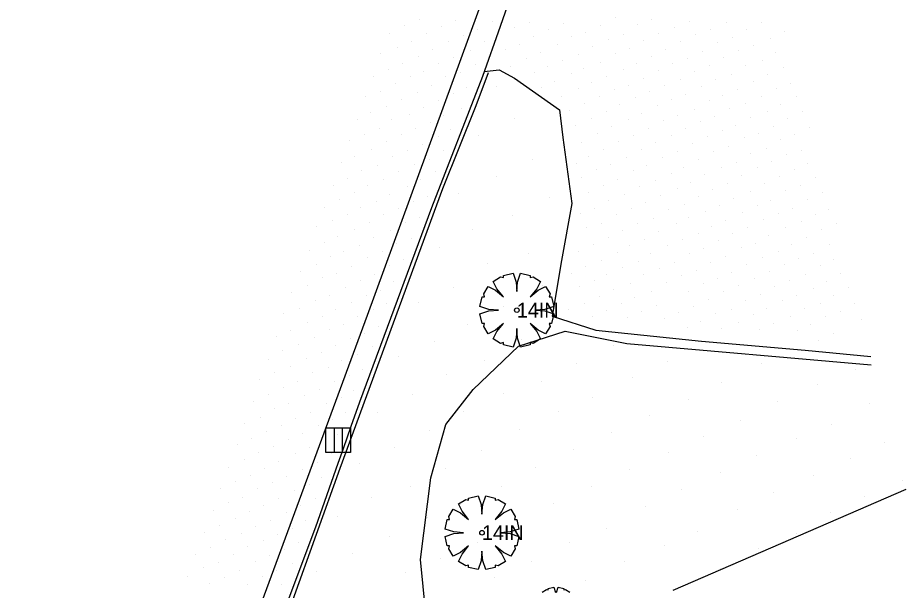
# Model space of a CAD drawing. Extents: x 1729983 to 1730242, y 468641 to 469019.
# Drawn here: x 1730133.1 to 1730241.6, y 468879.2 to 468949.2 of the extents above; entities that cross this region are included whole.
import ezdxf

# ---------------------------------------------------------------- set-up
doc = ezdxf.new("R2010")
doc.units = 0
for name, color, linetype in [('Default', 7, 'Continuous'), ('S_Curb_Type_1', 7, 'Continuous'), ('S_Drainage_CB', 7, 'Continuous'), ('S_Fencing_ChainLink', 7, 'Continuous'), ('S_Ground_SpotElevation', 7, 'Continuous'), ('S_Roadway_Drive_Paved', 7, 'Continuous'), ('S_Roadway_Edge_Pavement', 7, 'Continuous'), ('S_Roadway_Painted_Lines', 7, 'Continuous'), ('S_Text', 7, 'Continuous'), ('S_Trees_Bush_Line', 7, 'Continuous'), ('S_Trees_Decid_NonPay', 7, 'Continuous'), ('S_Trees_Decid_Pay', 7, 'Continuous')]:
    doc.layers.add(name, color=color, linetype=linetype)

# ---------------------------------------------------------------- blocks, each defined once
blk = doc.blocks.new('POINT_DISPLAY')
at = {"layer": 'Default'}
blk.add_line((0, 0), (0, 0), dxfattribs=at)

msp = doc.modelspace()

# ---------------------------------------------------------------- linework, layer by layer
at = {"layer": 'S_Curb_Type_1'}
msp.add_lwpolyline([(1730166.7, 468878.04), (1730172.48, 468894.17), (1730178.99, 468911.93), (1730185.01, 468928.36), (1730189.07, 468938.51), (1730190.59, 468942.51)], dxfattribs=at)
at = {"layer": 'S_Drainage_CB'}
for p, q in [((1730171.73, 468899.1), (1730171.73, 468896.1)), ((1730172.73, 468899.1), (1730172.73, 468896.1))]:
    msp.add_line(p, q, dxfattribs=at)
msp.add_lwpolyline([(1730170.73, 468899.1), (1730173.73, 468899.1), (1730173.73, 468896.1), (1730170.73, 468896.1)], close=True, dxfattribs=at)
at = {"layer": 'S_Fencing_ChainLink'}
msp.add_line((1730213.16, 468879.27), (1730241.65, 468891.6), dxfattribs=at)
at = {"layer": 'S_Roadway_Drive_Paved'}
msp.add_lwpolyline([(1730190.08, 468942.66), (1730191.89, 468942.87), (1730193.76, 468941.82), (1730199.29, 468937.96), (1730199.68, 468934.57), (1730200.79, 468926.52), (1730199.5, 468919.56), (1730198.39, 468912.74), (1730203.72, 468911.04), (1730216.64, 468909.68), (1730229.29, 468908.57), (1730237.33, 468907.81)], dxfattribs=at)
at = {"layer": 'S_Roadway_Edge_Pavement'}
msp.add_lwpolyline([(1730202.63, 468977.5), (1730198.74, 468966.66), (1730194.38, 468954.96), (1730192.03, 468948.15), (1730189.86, 468942.05), (1730183.64, 468926), (1730174.83, 468902.22), (1730173.78, 468899.25), (1730172.82, 468896.55), (1730172.2, 468894.75), (1730169.44, 468886.97), (1730164.5, 468873.71)], dxfattribs=at)
at = {"layer": 'S_Roadway_Painted_Lines'}
msp.add_lwpolyline([(1730094.8, 468656.26), (1730095.17, 468660.96), (1730096.08, 468669.98), (1730097.64, 468680.77), (1730099.58, 468691.95), (1730101.13, 468699.69), (1730104.77, 468714.07), (1730108.65, 468727.01), (1730112.54, 468738.83), (1730119.79, 468759.43), (1730137.2, 468807.81), (1730148.9, 468839.72), (1730160.49, 468871.27), (1730175.8, 468912.85), (1730190.41, 468952.88), (1730200.04, 468978.35)], dxfattribs=at)
at = {"layer": 'S_Trees_Bush_Line'}
msp.add_lwpolyline([(1730184.47, 468866.09), (1730183.27, 468873.09), (1730182.28, 468883.02), (1730183.53, 468892.98), (1730185.39, 468899.51), (1730188.73, 468903.8), (1730194.28, 468909.06), (1730199.95, 468910.92), (1730207.49, 468909.42), (1730237.35, 468906.81)], dxfattribs=at)
at = {"layer": 'S_Trees_Decid_NonPay'}
for points in [[(1730197.16, 468879.02), (1730197.69, 468879.34), (1730197.9, 468879.29), (1730197.9, 468879.45), (1730198.59, 468879.61), (1730198.8, 468878.97)], [(1730198.91, 468878.97), (1730199.12, 468879.61), (1730199.81, 468879.45), (1730199.81, 468879.29), (1730200.02, 468879.34), (1730200.55, 468879.02)]]:
    msp.add_lwpolyline(points, dxfattribs=at)
at = {"layer": 'S_Trees_Decid_Pay'}
for points in [[(1730191.81, 468913.48), (1730190.64, 468913.57), (1730189.55, 468913.93), (1730189.82, 468915.11), (1730190.1, 468915.11), (1730190.01, 468915.47), (1730190.55, 468916.37), (1730191.45, 468915.92), (1730192.44, 468915.11), (1730191.63, 468916.1), (1730191.18, 468917), (1730192.08, 468917.54), (1730192.44, 468917.45), (1730192.44, 468917.72), (1730193.61, 468918), (1730193.97, 468916.91), (1730194.06, 468915.74), (1730194.16, 468916.91), (1730194.52, 468918), (1730195.69, 468917.72), (1730195.69, 468917.45), (1730196.05, 468917.54), (1730196.95, 468917), (1730196.5, 468916.1), (1730195.69, 468915.11), (1730196.68, 468915.92), (1730197.58, 468916.37), (1730198.12, 468915.47), (1730198.03, 468915.11), (1730198.31, 468915.11), (1730198.58, 468913.93), (1730197.49, 468913.57), (1730196.32, 468913.48), (1730197.49, 468913.39), (1730198.58, 468913.03), (1730198.31, 468911.86), (1730198.03, 468911.86), (1730198.12, 468911.5), (1730197.58, 468910.6), (1730196.68, 468911.05), (1730195.69, 468911.86), (1730196.5, 468910.87), (1730196.95, 468909.97), (1730196.05, 468909.42), (1730195.69, 468909.51), (1730195.69, 468909.24), (1730194.52, 468908.97), (1730194.16, 468910.06), (1730194.06, 468911.23), (1730193.97, 468910.06), (1730193.61, 468908.97), (1730192.44, 468909.24), (1730192.44, 468909.51), (1730192.08, 468909.42), (1730191.18, 468909.97), (1730191.63, 468910.87), (1730192.44, 468911.86), (1730191.45, 468911.05), (1730190.55, 468910.6), (1730190.01, 468911.5), (1730190.1, 468911.86), (1730189.82, 468911.86), (1730189.55, 468913.03), (1730190.64, 468913.39), (1730191.81, 468913.48)], [(1730187.54, 468886.28), (1730186.37, 468886.37), (1730185.28, 468886.73), (1730185.56, 468887.91), (1730185.83, 468887.91), (1730185.74, 468888.27), (1730186.28, 468889.17), (1730187.18, 468888.72), (1730188.17, 468887.91), (1730187.36, 468888.9), (1730186.91, 468889.8), (1730187.81, 468890.34), (1730188.17, 468890.25), (1730188.17, 468890.52), (1730189.34, 468890.8), (1730189.71, 468889.71), (1730189.8, 468888.54), (1730189.89, 468889.71), (1730190.25, 468890.8), (1730191.42, 468890.52), (1730191.42, 468890.25), (1730191.78, 468890.34), (1730192.68, 468889.8), (1730192.23, 468888.9), (1730191.42, 468887.91), (1730192.41, 468888.72), (1730193.32, 468889.17), (1730193.86, 468888.27), (1730193.77, 468887.91), (1730194.04, 468887.91), (1730194.31, 468886.73), (1730193.23, 468886.37), (1730192.05, 468886.28), (1730193.23, 468886.19), (1730194.31, 468885.83), (1730194.04, 468884.66), (1730193.77, 468884.66), (1730193.86, 468884.3), (1730193.32, 468883.4), (1730192.41, 468883.85), (1730191.42, 468884.66), (1730192.23, 468883.67), (1730192.68, 468882.77), (1730191.78, 468882.22), (1730191.42, 468882.31), (1730191.42, 468882.04), (1730190.25, 468881.77), (1730189.89, 468882.86), (1730189.8, 468884.03), (1730189.71, 468882.86), (1730189.34, 468881.77), (1730188.17, 468882.04), (1730188.17, 468882.31), (1730187.81, 468882.22), (1730186.91, 468882.77), (1730187.36, 468883.67), (1730188.17, 468884.66), (1730187.18, 468883.85), (1730186.28, 468883.4), (1730185.74, 468884.3), (1730185.83, 468884.66), (1730185.56, 468884.66), (1730185.28, 468885.83), (1730186.37, 468886.19), (1730187.54, 468886.28)]]:
    msp.add_lwpolyline(points, dxfattribs=at)
for centre in [(1730194.06, 468913.48), (1730189.8, 468886.28)]:
    msp.add_circle(centre, 0.283, dxfattribs=at)

# ---------------------------------------------------------------- block references
at = {"layer": 'S_Ground_SpotElevation'}
for p in [(1730180.32, 468948.21), (1730182.17, 468948.97), (1730186.61, 468948.84), (1730191.05, 468948.8), (1730195.6, 468948.64), (1730199.78, 468948.56), (1730204.25, 468948.33), (1730206.06, 468949.19), (1730208.76, 468948.37), (1730210.5, 468949.03), (1730215.13, 468948.78), (1730219.62, 468948.6), (1730223.95, 468948.63), (1730178.44, 468947.25), (1730183.07, 468947.27), (1730184.9, 468948.11), (1730189.22, 468947.78), (1730193.74, 468947.98), (1730197.98, 468947.81), (1730202.51, 468947.45), (1730207.06, 468947.18), (1730211.36, 468947.34), (1730213.3, 468948.04), (1730215.88, 468947.22), (1730217.72, 468947.8), (1730222.18, 468947.8), (1730226.76, 468947.52), (1730181.13, 468946.34), (1730185.72, 468946.31), (1730187.51, 468947.01), (1730190.07, 468946.29), (1730191.71, 468947), (1730194.36, 468945.98), (1730196.13, 468946.9), (1730199.04, 468945.98), (1730200.75, 468946.87), (1730205.2, 468946.56), (1730209.51, 468946.38), (1730214.03, 468946.34), (1730218.61, 468946.21), (1730220.38, 468946.83), (1730225, 468946.64), (1730177.38, 468944.89), (1730179.42, 468945.63), (1730183.74, 468945.28), (1730188.34, 468945.21), (1730192.69, 468945.29), (1730197.01, 468944.93), (1730203.34, 468945.76), (1730206.16, 468944.88), (1730207.79, 468945.49), (1730212.18, 468945.38), (1730216.79, 468945.08), (1730221.2, 468945.25), (1730222.93, 468945.87), (1730225.7, 468944.97), (1730182, 468944.47), (1730186.34, 468944.41), (1730190.71, 468944.28), (1730195.28, 468944.22), (1730199.59, 468944.04), (1730201.56, 468944.7), (1730210.51, 468944.47), (1730214.94, 468944.28), (1730219.32, 468944.35), (1730224.05, 468944.05), (1730178.39, 468942.88), (1730180.09, 468943.67), (1730184.54, 468943.67), (1730189.02, 468943.47), (1730193.31, 468943.29), (1730197.79, 468943.24), (1730202.25, 468943.06), (1730204.26, 468943.69), (1730207.04, 468942.88), (1730208.63, 468943.65), (1730211.32, 468942.79), (1730213.09, 468943.6), (1730217.55, 468943.33), (1730222.02, 468943.43), (1730226.6, 468943.1), (1730176.57, 468942.06), (1730181.11, 468942), (1730182.69, 468942.66), (1730185.38, 468941.98), (1730187.19, 468942.53), (1730196.21, 468942.48), (1730200.69, 468942.38), (1730204.96, 468942), (1730209.48, 468941.77), (1730214.1, 468941.69), (1730215.73, 468942.67), (1730218.33, 468941.71), (1730220.27, 468942.34), (1730224.67, 468942.29), (1730179.28, 468941.2), (1730183.59, 468940.91), (1730187.94, 468940.73), (1730191.59, 468940.86), (1730197.05, 468940.73), (1730198.69, 468941.41), (1730201.58, 468940.53), (1730203.23, 468941.32), (1730207.7, 468940.91), (1730212.09, 468940.9), (1730216.59, 468940.83), (1730222.96, 468941.41), (1730225.77, 468940.62), (1730227.45, 468941.21), (1730175.54, 468939.55), (1730177.43, 468940.2), (1730181.93, 468940.05), (1730186.32, 468939.94), (1730199.48, 468939.61), (1730204.12, 468939.61), (1730206, 468940.41), (1730210.23, 468940.2), (1730214.7, 468939.89), (1730219.18, 468939.69), (1730221.03, 468940.5), (1730223.92, 468939.56), (1730228.18, 468939.6), (1730178.16, 468938.4), (1730180.01, 468939.21), (1730184.47, 468939.12), (1730202.28, 468938.71), (1730206.66, 468938.57), (1730208.57, 468939.43), (1730211.28, 468938.45), (1730212.92, 468939.19), (1730217.6, 468939.05), (1730221.95, 468938.74), (1730226.27, 468938.62), (1730176.22, 468937.59), (1730180.91, 468937.37), (1730182.63, 468938.23), (1730185.12, 468937.31), (1730187.24, 468938.12), (1730200.5, 468937.92), (1730204.98, 468937.73), (1730209.31, 468937.52), (1730213.74, 468937.32), (1730215.71, 468937.97), (1730220.09, 468938.13), (1730224.68, 468937.75), (1730229.02, 468937.77), (1730174.58, 468936.82), (1730178.79, 468936.74), (1730183.45, 468936.45), (1730193.83, 468936.88), (1730203.18, 468936.93), (1730207.66, 468936.73), (1730211.99, 468936.64), (1730216.53, 468936.52), (1730218.22, 468937.16), (1730222.64, 468937.05), (1730227.19, 468936.91), (1730177.23, 468935.72), (1730181.63, 468935.65), (1730185.97, 468935.6), (1730201.25, 468936.05), (1730205.64, 468935.88), (1730210.2, 468935.71), (1730214.73, 468935.64), (1730219.17, 468935.46), (1730220.84, 468936.07), (1730225.47, 468935.95), (1730229.84, 468935.81), (1730173.58, 468934.21), (1730175.49, 468934.94), (1730178.13, 468934.1), (1730179.96, 468934.93), (1730184.45, 468934.7), (1730189.34, 468934.82), (1730202, 468934.03), (1730203.86, 468935.05), (1730206.49, 468934.08), (1730208.29, 468934.79), (1730212.96, 468934.83), (1730217.33, 468934.68), (1730221.87, 468934.53), (1730223.56, 468935.03), (1730226.25, 468934.37), (1730228, 468934.92), (1730176.3, 468933.07), (1730180.73, 468933.04), (1730182.58, 468933.78), (1730185.14, 468933.03), (1730204.67, 468933.17), (1730209.29, 468933.12), (1730211.05, 468933.98), (1730215.56, 468933.81), (1730219.9, 468933.5), (1730224.55, 468933.24), (1730228.89, 468933.04), (1730174.25, 468932.27), (1730178.89, 468932.22), (1730183.37, 468931.92), (1730196.03, 468931.93), (1730202.85, 468932.28), (1730207.43, 468932.16), (1730211.9, 468932.15), (1730213.65, 468932.86), (1730216.31, 468931.86), (1730218.09, 468932.84), (1730222.64, 468932.59), (1730227.02, 468932.47), (1730172.58, 468931.51), (1730176.98, 468931.2), (1730181.6, 468931.3), (1730201.35, 468931.4), (1730205.55, 468931.28), (1730209.9, 468931.2), (1730214.43, 468930.96), (1730219.09, 468930.86), (1730220.87, 468931.51), (1730223.47, 468930.86), (1730225.23, 468931.62), (1730229.62, 468931.45), (1730175.02, 468930.51), (1730179.54, 468930.45), (1730184.08, 468930.37), (1730191.59, 468929.81), (1730201.91, 468929.71), (1730203.76, 468930.64), (1730208.27, 468930.52), (1730212.94, 468930.21), (1730217.04, 468930.11), (1730221.57, 468929.93), (1730226.12, 468929.83), (1730228, 468930.65), (1730230.55, 468929.68), (1730171.62, 468928.72), (1730173.36, 468929.62), (1730175.85, 468928.7), (1730177.74, 468929.45), (1730180.67, 468928.6), (1730182.32, 468929.41), (1730204.65, 468928.71), (1730206.34, 468929.43), (1730209.06, 468928.62), (1730210.97, 468929.3), (1730215.31, 468929.07), (1730219.75, 468929.01), (1730224.29, 468929), (1730228.67, 468928.72), (1730174.2, 468927.81), (1730178.51, 468927.6), (1730186.88, 468927.73), (1730202.82, 468927.82), (1730207.16, 468927.56), (1730213.72, 468928.33), (1730218, 468928.27), (1730222.65, 468928.04), (1730226.88, 468928.07), (1730231.4, 468927.81), (1730172.34, 468926.99), (1730176.96, 468926.74), (1730181.49, 468926.73), (1730183.19, 468927.42), (1730198.03, 468927.27), (1730205.32, 468926.89), (1730209.84, 468926.68), (1730211.62, 468927.45), (1730216.25, 468927.39), (1730220.56, 468927.12), (1730225.1, 468926.91), (1730229.56, 468926.98), (1730170.56, 468926.06), (1730174.92, 468925.99), (1730179.58, 468925.87), (1730201.87, 468925.34), (1730203.55, 468925.94), (1730208.02, 468925.96), (1730212.65, 468925.84), (1730214.49, 468926.37), (1730217.07, 468925.51), (1730218.86, 468926.25), (1730221.67, 468925.41), (1730223.43, 468926.27), (1730227.78, 468925.92), (1730232.17, 468925.82), (1730171.51, 468924.47), (1730173.31, 468925.2), (1730177.76, 468925.16), (1730182.19, 468924.75), (1730193.48, 468925.07), (1730206.23, 468925.12), (1730210.71, 468924.71), (1730215.09, 468924.79), (1730219.59, 468924.49), (1730224.18, 468924.51), (1730226.03, 468925.26), (1730228.81, 468924.29), (1730230.57, 468925.22), (1730169.55, 468923.75), (1730174.18, 468923.35), (1730176.04, 468924.18), (1730178.58, 468923.18), (1730180.46, 468924.19), (1730188.67, 468923.36), (1730202.63, 468923.52), (1730204.42, 468924.05), (1730206.98, 468923.18), (1730208.79, 468924.1), (1730213.56, 468924.05), (1730217.83, 468923.66), (1730222.22, 468923.62), (1730226.88, 468923.59), (1730231.24, 468923.31), (1730233.12, 468924.05), (1730172.13, 468922.52), (1730176.57, 468922.33), (1730181.2, 468922.19), (1730205.28, 468922.3), (1730209.69, 468922.17), (1730211.43, 468923.07), (1730214.29, 468922.17), (1730216.2, 468922.85), (1730220.42, 468922.79), (1730224.85, 468922.56), (1730229.46, 468922.4), (1730170.52, 468921.72), (1730174.85, 468921.43), (1730179.34, 468921.6), (1730184.57, 468921.12), (1730203.4, 468921.56), (1730207.85, 468921.43), (1730212.47, 468921.33), (1730216.91, 468921.06), (1730218.71, 468921.99), (1730221.53, 468921.08), (1730223.28, 468921.64), (1730227.66, 468921.49), (1730232.32, 468921.48), (1730168.72, 468920.83), (1730171.24, 468920.06), (1730172.89, 468920.68), (1730175.75, 468919.89), (1730177.63, 468920.65), (1730195.5, 468920.38), (1730201.57, 468920.61), (1730206.33, 468920.48), (1730210.44, 468920.4), (1730215.17, 468920.4), (1730219.56, 468920.01), (1730224.02, 468919.9), (1730225.99, 468920.65), (1730230.33, 468920.45), (1730169.59, 468919.03), (1730173.88, 468918.85), (1730178.48, 468918.89), (1730180.24, 468919.65), (1730190.51, 468919.17), (1730202.46, 468918.82), (1730204.4, 468919.53), (1730208.91, 468919.45), (1730213.29, 468919.26), (1730217.75, 468919.32), (1730222.12, 468919.12), (1730226.75, 468919), (1730228.52, 468919.77), (1730231.19, 468918.89), (1730232.81, 468919.69), (1730167.57, 468918.18), (1730172.08, 468917.92), (1730176.66, 468917.79), (1730200.74, 468918.02), (1730205.04, 468917.81), (1730207.02, 468918.74), (1730209.54, 468917.8), (1730211.53, 468918.6), (1730214.23, 468917.74), (1730216, 468918.34), (1730220.32, 468918.14), (1730224.89, 468918.15), (1730229.29, 468917.8), (1730233.65, 468917.91), (1730170.36, 468917.41), (1730174.91, 468917.16), (1730179.03, 468916.93), (1730203.54, 468917.12), (1730207.92, 468916.77), (1730212.3, 468916.84), (1730216.88, 468916.68), (1730218.53, 468917.36), (1730223.11, 468917.39), (1730227.44, 468917.1), (1730231.92, 468917.01), (1730166.47, 468915.6), (1730168.5, 468916.44), (1730173.09, 468916.27), (1730177.44, 468915.94), (1730186.28, 468916.3), (1730197.15, 468916.51), (1730201.69, 468916.35), (1730205.87, 468916.06), (1730210.47, 468915.79), (1730215.03, 468915.8), (1730219.36, 468915.72), (1730221.2, 468916.49), (1730225.56, 468916.35), (1730230.34, 468916.16), (1730234.61, 468916.21), (1730169.44, 468914.67), (1730171.22, 468915.33), (1730173.81, 468914.47), (1730175.68, 468915.25), (1730204.16, 468915.09), (1730208.48, 468915.03), (1730217.49, 468914.79), (1730222, 468914.63), (1730223.79, 468915.44), (1730226.52, 468914.66), (1730228.25, 468915.28), (1730232.8, 468915.25), (1730167.5, 468913.74), (1730171.87, 468913.57), (1730176.56, 468913.58), (1730178.12, 468914.32), (1730182.01, 468914.4), (1730192.48, 468913.96), (1730200.43, 468913.61), (1730202.37, 468914.31), (1730204.96, 468913.4), (1730206.87, 468914.33), (1730211.14, 468914.06), (1730215.65, 468913.95), (1730220.27, 468913.62), (1730224.63, 468913.64), (1730229.16, 468913.67), (1730231.12, 468914.28), (1730235.37, 468914.32), (1730165.5, 468913.01), (1730170.28, 468912.69), (1730174.64, 468912.72), (1730203.3, 468912.69), (1730207.58, 468912.57), (1730209.35, 468913.31), (1730212.06, 468912.45), (1730213.85, 468913.15), (1730218.37, 468913.11), (1730222.95, 468912.94), (1730227.46, 468912.65), (1730231.83, 468912.65), (1730233.58, 468913.36), (1730236.19, 468912.3), (1730168.46, 468911.98), (1730172.91, 468911.69), (1730177.19, 468911.53), (1730188.01, 468911.77), (1730214.88, 468911.34), (1730216.47, 468912.06), (1730219.12, 468911.25), (1730221.18, 468911.94), (1730225.47, 468911.84), (1730229.91, 468911.74), (1730164.7, 468910.21), (1730166.37, 468910.97), (1730169.29, 468910.19), (1730171.12, 468911.07), (1730175.44, 468910.64), (1730223.7, 468911.07), (1730228.36, 468910.98), (1730232.77, 468910.62), (1730167.43, 468909.25), (1730171.95, 468909.11), (1730173.79, 468910.02), (1730183.95, 468909.59), (1730194.59, 468909.95), (1730205.83, 468909.15), (1730230.93, 468909.77), (1730165.47, 468908.49), (1730170.15, 468908.35), (1730174.59, 468908.06), (1730176.42, 468909.01), (1730163.71, 468907.47), (1730168.33, 468907.54), (1730172.64, 468907.33), (1730179.63, 468907.79), (1730190.11, 468907.38), (1730201.39, 468906.99), (1730212.53, 468907.25), (1730224.01, 468906.96), (1730164.4, 468905.84), (1730166.37, 468906.63), (1730169.11, 468905.82), (1730170.99, 468906.49), (1730175.16, 468906.25), (1730235.39, 468906.17), (1730162.66, 468904.95), (1730167.27, 468904.74), (1730171.83, 468904.72), (1730173.56, 468905.45), (1730185.47, 468905.6), (1730197.04, 468904.78), (1730208.16, 468905.22), (1730165.52, 468904.04), (1730169.97, 468903.82), (1730174.14, 468903.62), (1730219.09, 468904.64), (1730230.79, 468904.41), (1730163.65, 468903.13), (1730168.16, 468903), (1730172.61, 468902.79), (1730181.31, 468903.13), (1730192.39, 468903.34), (1730203.26, 468902.79), (1730215.02, 468902.62), (1730161.91, 468902.35), (1730166.16, 468902.12), (1730170.77, 468902.01), (1730225.88, 468902.37), (1730237.11, 468902.02), (1730162.68, 468900.42), (1730164.4, 468901.43), (1730168.87, 468901.01), (1730173.14, 468900.99), (1730177.07, 468900.98), (1730187.53, 468901.13), (1730199.13, 468901.05), (1730210.29, 468900.63), (1730160.82, 468899.66), (1730165.27, 468899.36), (1730167.07, 468900.22), (1730169.85, 468899.36), (1730171.56, 468900.07), (1730221.41, 468900), (1730232.55, 468899.46), (1730163.49, 468898.64), (1730167.92, 468898.42), (1730172.2, 468898.29), (1730183.34, 468898.76), (1730194.4, 468898.89), (1730205.6, 468898.51), (1730161.58, 468897.79), (1730166.12, 468897.69), (1730170.67, 468897.62), (1730216.82, 468898.09), (1730228.22, 468897.84), (1730238.99, 468897.31), (1730159.9, 468897), (1730162.52, 468896.03), (1730164.35, 468896.8), (1730168.78, 468896.71), (1730179.15, 468896.73), (1730189.7, 468896.29), (1730200.95, 468896.43), (1730212.57, 468896.12), (1730160.72, 468895.21), (1730164.92, 468894.97), (1730167.01, 468895.99), (1730171.39, 468895.9), (1730223.29, 468895.68), (1730234.89, 468895.35), (1730158.82, 468894.24), (1730163.27, 468894.15), (1730167.84, 468893.99), (1730169.67, 468894.81), (1730174.81, 468894.76), (1730185.35, 468894.14), (1730196.33, 468894.25), (1730207.83, 468893.96), (1730161.52, 468893.24), (1730165.93, 468893.1), (1730170.23, 468893.01), (1730218.9, 468893.66), (1730230.32, 468893.33), (1730159.73, 468892.52), (1730162.31, 468891.66), (1730164.2, 468892.41), (1730168.67, 468892.16), (1730181.05, 468891.91), (1730192.13, 468891.87), (1730203.16, 468891.96), (1730241.25, 468892.65), (1730157.85, 468891.65), (1730160.54, 468890.58), (1730166.91, 468891.48), (1730176.26, 468890.59), (1730214.23, 468891.54), (1730225.45, 468891.14), (1730236.56, 468890.7), (1730158.78, 468889.93), (1730163.16, 468889.6), (1730164.96, 468890.51), (1730167.64, 468889.63), (1730169.43, 468890.45), (1730187.2, 468889.78), (1730198.58, 468889.8), (1730209.8, 468889.5), (1730156.97, 468889.04), (1730161.44, 468888.87), (1730165.92, 468888.72), (1730221.01, 468889.1), (1730232.42, 468888.72), (1730159.64, 468888.06), (1730163.98, 468887.83), (1730168.24, 468887.79), (1730172.16, 468888.26), (1730183.18, 468888.09), (1730193.98, 468887.73), (1730155.93, 468886.29), (1730157.74, 468887.12), (1730162.17, 468887.04), (1730166.66, 468886.85), (1730204.96, 468886.82), (1730216.13, 468886.48), (1730158.42, 468885.49), (1730160.39, 468886.2), (1730163.11, 468885.3), (1730164.8, 468886), (1730178.51, 468885.86), (1730228.23, 468886.19), (1730156.64, 468884.46), (1730161.19, 468884.61), (1730165.7, 468884.17), (1730167.35, 468885.04), (1730189.29, 468885.09), (1730200.45, 468885.05), (1730212.06, 468884.71), (1730223.65, 468884.33), (1730154.84, 468883.59), (1730159.42, 468883.67), (1730163.81, 468883.51), (1730174.01, 468883.73), (1730184.76, 468883.1), (1730155.79, 468882.03), (1730157.63, 468882.67), (1730162.08, 468882.73), (1730166.61, 468882.48), (1730195.91, 468882.77), (1730207.26, 468882.74), (1730218.99, 468881.91), (1730153.84, 468880.95), (1730160.22, 468881.64), (1730162.93, 468880.89), (1730164.68, 468881.69), (1730169.63, 468881.58), (1730180.51, 468881.36), (1730156.49, 468880.03), (1730158.38, 468880.8), (1730161.12, 468879.9), (1730165.34, 468879.93), (1730191.3, 468880.77), (1730202.5, 468880.45)]:
    msp.add_blockref('POINT_DISPLAY', p, dxfattribs=at)

# ---------------------------------------------------------------- texts
at = {"layer": 'S_Text'}
for p in [(1730194.06, 468912.58), (1730189.8, 468885.38)]:
    msp.add_text('14IN', height=1.8, dxfattribs=at).set_placement(p)

doc.saveas('drawing.dxf')
